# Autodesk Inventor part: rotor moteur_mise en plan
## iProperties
Created: 2011-10
Part Number: rotor moteur_mise en plan
Document SubType Name: Modeling
Designer: Bruno
Author: Bruno
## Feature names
1. Base1
